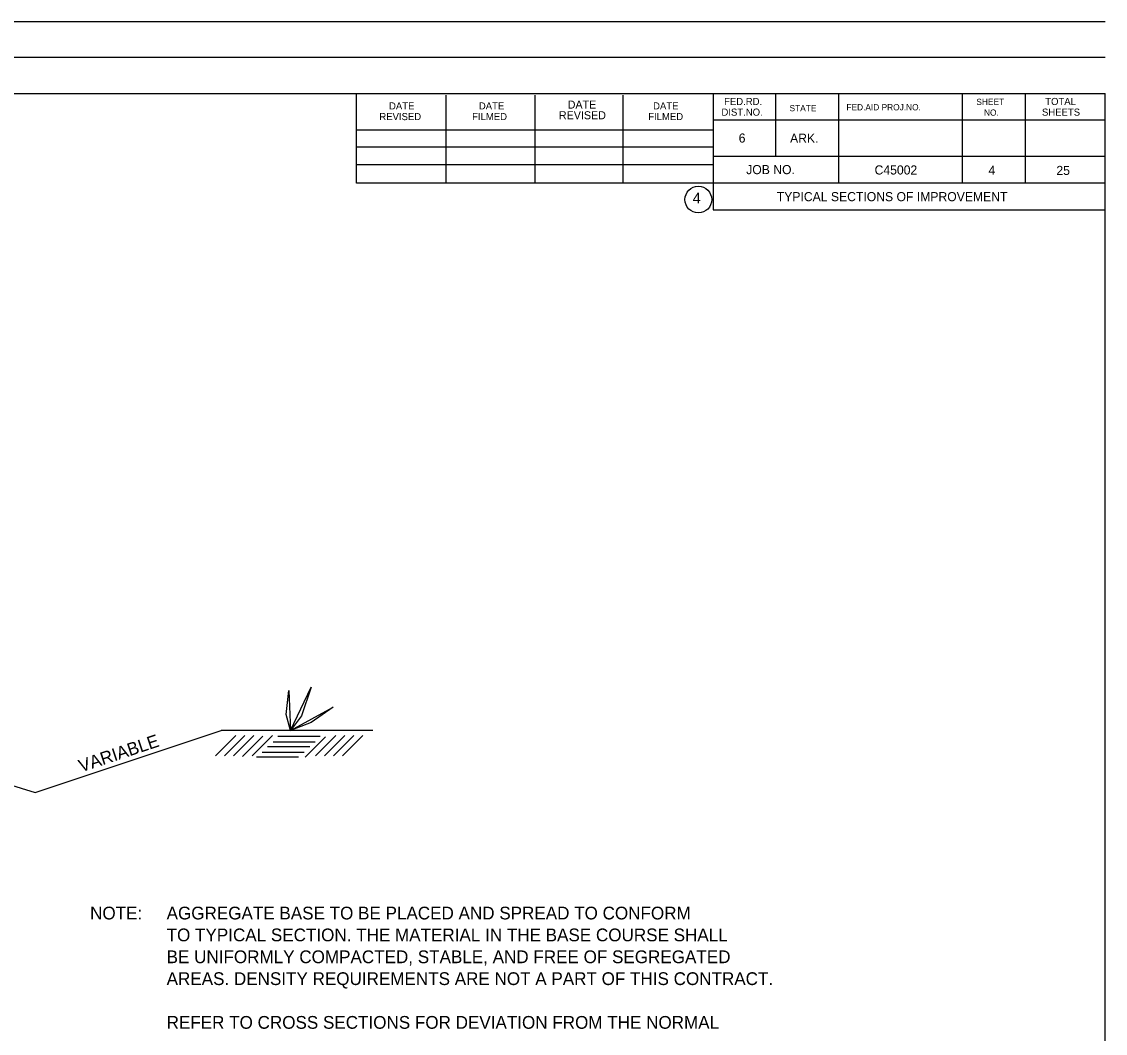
# Model space of a CAD drawing. Extents: x 1944905 to 1956777, y 763871 to 764977.
# Drawn here: x 1945928 to 1946523, y 764421 to 764977 of the extents above; entities that cross this region are included whole.
import ezdxf

# ---------------------------------------------------------------- set-up
doc = ezdxf.new("R2010")
doc.units = 0
doc.layers.add('Default', color=7, linetype='Continuous')

msp = doc.modelspace()

# ---------------------------------------------------------------- linework, layer by layer
at = {"layer": 'Default'}
for p, q in [((1946523.23, 764976.71), (1944904.57, 764976.71)), ((1946523.23, 764957.02), (1944904.56, 764957.02)), ((1944942.32, 764937.29), (1946523.23, 764937.29)), ((1946111.92, 764887.95), (1946111.91, 764937.29)), ((1946161.25, 764887.95), (1946161.25, 764936.31)), ((1946210.1, 764887.95), (1946210.1, 764936.31)), ((1946258.46, 764887.95), (1946258.47, 764936.31)), ((1946307.8, 764937.29), (1946307.8, 764873.29)), ((1946342, 764937.29), (1946342, 764902.6)), ((1946376.68, 764937.29), (1946376.68, 764887.95)), ((1946444.58, 764937.29), (1946444.58, 764887.95)), ((1946479.26, 764937.29), (1946479.26, 764887.95)), ((1946523.23, 763910.07), (1946523.23, 764937.29)), ((1946523.23, 764922.63), (1946307.81, 764922.63)), ((1946111.91, 764917.26), (1946307.8, 764917.26)), ((1946111.91, 764907.98), (1946307.8, 764907.98)), ((1946111.92, 764898.21), (1946307.8, 764898.21)), ((1946523.23, 764902.6), (1946307.8, 764902.6)), ((1946523.23, 764887.95), (1946111.92, 764887.95)), ((1946307.8, 764873.29), (1946523.23, 764873.29)), ((1946073.37, 764596.17), (1946074.8, 764609.4)), ((1946074.8, 764609.4), (1946075.77, 764587.53)), ((1946075.77, 764587.53), (1946087.06, 764611.32)), ((1946087.06, 764611.32), (1946081.78, 764595.46)), ((1946075.77, 764587.53), (1946073.37, 764596.17)), ((1946075.77, 764587.53), (1946099.07, 764600.26)), ((1946081.78, 764595.46), (1946075.77, 764587.53)), ((1946099.07, 764600.26), (1946087.06, 764591.85)), ((1945806.69, 764593.11), (1945935.48, 764553.32)), ((1946087.06, 764591.85), (1946075.77, 764587.53)), ((1945935.48, 764553.32), (1946037.56, 764587.35)), ((1946045.67, 764584.7), (1946034.47, 764573.5)), ((1946120.96, 764587.35), (1946037.56, 764587.35)), ((1946050.6, 764584.7), (1946039.41, 764573.5)), ((1946055.54, 764584.7), (1946044.35, 764573.5)), ((1946060.46, 764584.33), (1946049.27, 764573.14)), ((1946065.76, 764584.7), (1946054.57, 764573.5)), ((1946068.8, 764584.33), (1946091.93, 764584.33)), ((1946094.97, 764583.95), (1946083.78, 764572.75)), ((1946100.66, 764584.7), (1946089.47, 764573.5)), ((1946105.6, 764584.7), (1946094.4, 764573.5)), ((1946110.52, 764584.7), (1946099.32, 764573.5)), ((1946115.45, 764584.7), (1946104.26, 764573.5)), ((1946063.11, 764578.63), (1946086.25, 764578.63)), ((1946066.15, 764581.29), (1946089.28, 764581.29)), ((1946057.04, 764572.94), (1946080.18, 764572.94)), ((1946060.08, 764575.59), (1946083.21, 764575.59))]:
    msp.add_line(p, q, dxfattribs=at)
msp.add_circle((1946299.69, 764879.01), 7.33, dxfattribs=at)

# ---------------------------------------------------------------- texts
for s, height, p in [('FED.RD.', 3.91, (1946313.84, 764930.94)), ('SHEET', 3.42, (1946452.4, 764930.94)), ('TOTAL', 3.91, (1946490.23, 764930.94)), ('DATE', 3.91, (1946129.81, 764928.49)), ('DATE', 3.91, (1946179.15, 764928.49)), ('DATE', 4.396, (1946227.95, 764928.98)), ('DATE', 3.91, (1946274.84, 764928.49)), ('DIST.NO.', 3.91, (1946312.39, 764925.08)), ('STATE', 3.42, (1946349.8, 764927.52)), ('FED.AID PROJ.NO.', 3.4203, (1946381.03, 764928.01)), ('NO.', 3.42, (1946456.59, 764925.08)), ('SHEETS', 3.91, (1946488.44, 764925.08)), ('REVISED', 3.91, (1946124.5, 764922.63)), ('FILMED', 3.91, (1946175.45, 764922.63)), ('REVISED', 4.396, (1946223.12, 764923.12)), ('FILMED', 3.91, (1946272.17, 764922.63)), ('6', 5, (1946321.87, 764910.32)), ('ARK.', 5, (1946350.08, 764910.21)), ('JOB NO.', 5, (1946325.99, 764892.97)), ('C45002', 5, (1946396.5, 764892.78)), ('4', 5, (1946459.08, 764892.68)), ('25', 5, (1946496.34, 764892.51)), ('4', 5.86, (1946296.6, 764876.89)), ('TYPICAL SECTIONS OF IMPROVEMENT', 5, (1946342.79, 764878.12)), ('NOTE:', 7.005, (1945965.63, 764483.68)), ('AGGREGATE BASE TO BE PLACED AND SPREAD TO CONFORM', 7.0054, (1946007.66, 764483.68)), ('TO TYPICAL SECTION. THE MATERIAL IN THE BASE COURSE SHALL', 7.0054, (1946007.66, 764471.67)), ('BE UNIFORMLY COMPACTED, STABLE, AND FREE OF SEGREGATED', 7.0054, (1946007.66, 764459.66)), ('AREAS. DENSITY REQUIREMENTS ARE NOT A PART OF THIS CONTRACT.', 7.0054, (1946007.66, 764447.65)), ('REFER TO CROSS SECTIONS FOR DEVIATION FROM THE NORMAL', 7.0054, (1946007.66, 764423.64))]:
    msp.add_text(s, height=height, dxfattribs=at).set_placement(p)
msp.add_text('VARIABLE', height=7, rotation=18.37249, dxfattribs=at).set_placement((1945960.7, 764564.43))

doc.saveas('drawing.dxf')
